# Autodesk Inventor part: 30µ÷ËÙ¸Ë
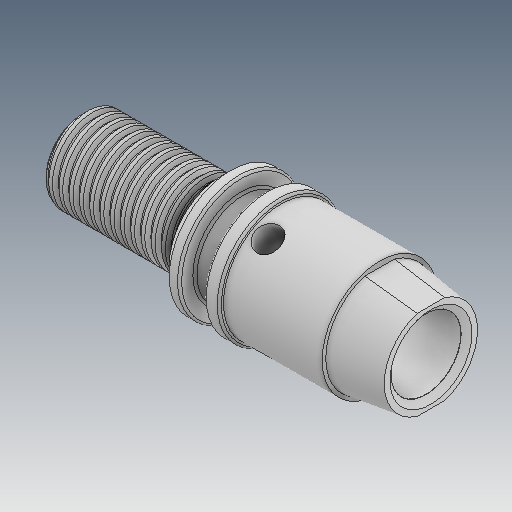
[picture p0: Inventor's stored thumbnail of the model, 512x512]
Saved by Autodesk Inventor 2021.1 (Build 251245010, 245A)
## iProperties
Created: 2019-12
Part Number: 30µ÷ËÙ¸Ë
Material: Ogólny
Document SubType Name: Modeling
Designer: user
Density: 1 g/cm^3
Appearance: Domyślna
Author: user
Revision Number: ÈÎºÎ
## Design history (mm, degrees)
feature "ÊäÈë1"
node "Bryła1"
